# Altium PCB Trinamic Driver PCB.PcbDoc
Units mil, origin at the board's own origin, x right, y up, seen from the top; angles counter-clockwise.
Board outline 920 x 2060 mil, 2 copper layers (Top Layer, Bottom Layer); 22 components, 34 nets, 111 pads, 14 vias.
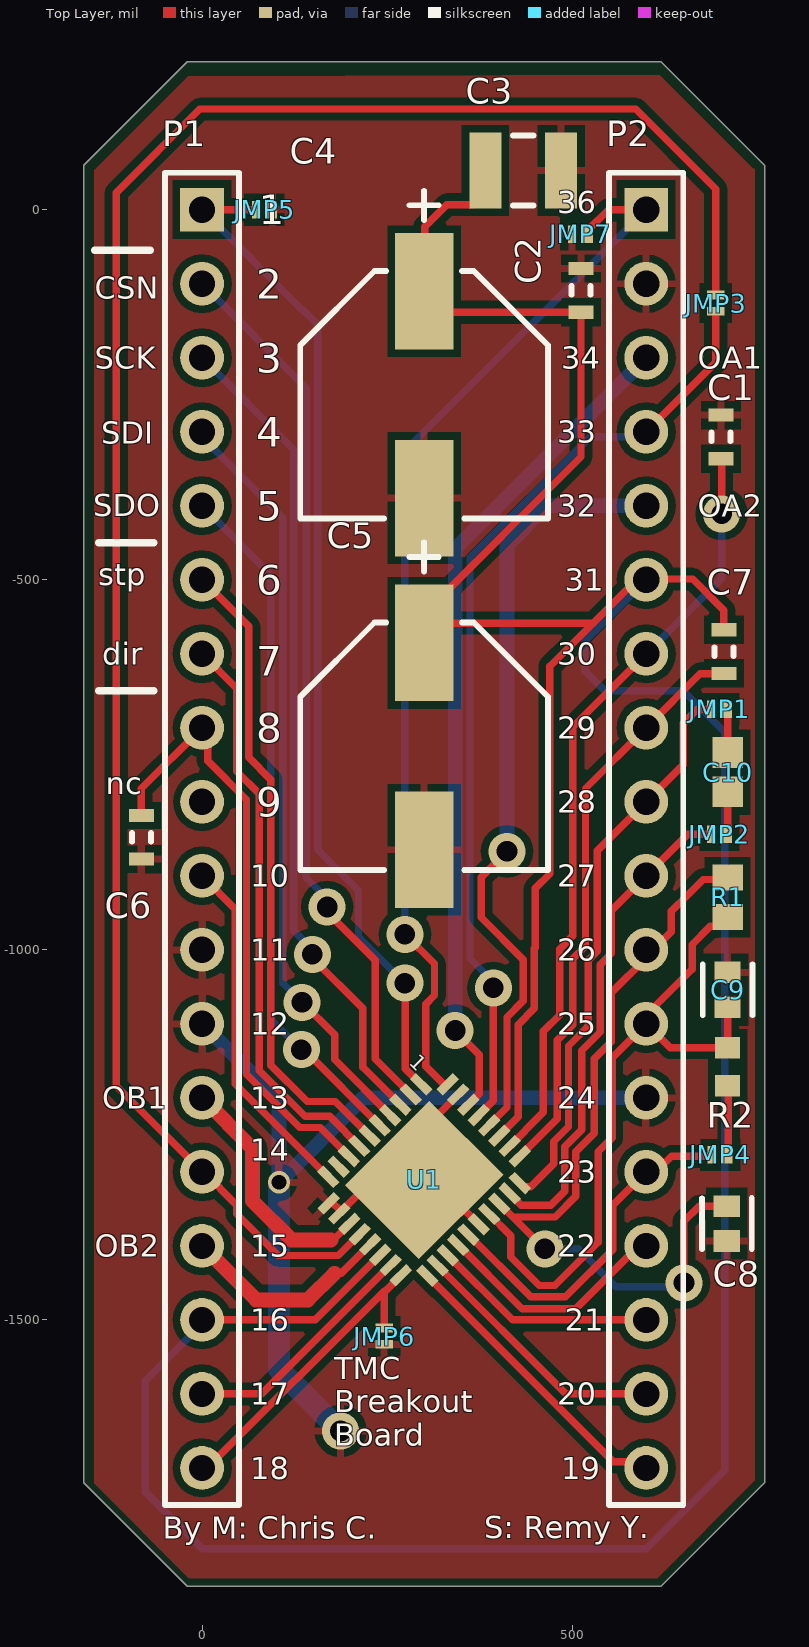
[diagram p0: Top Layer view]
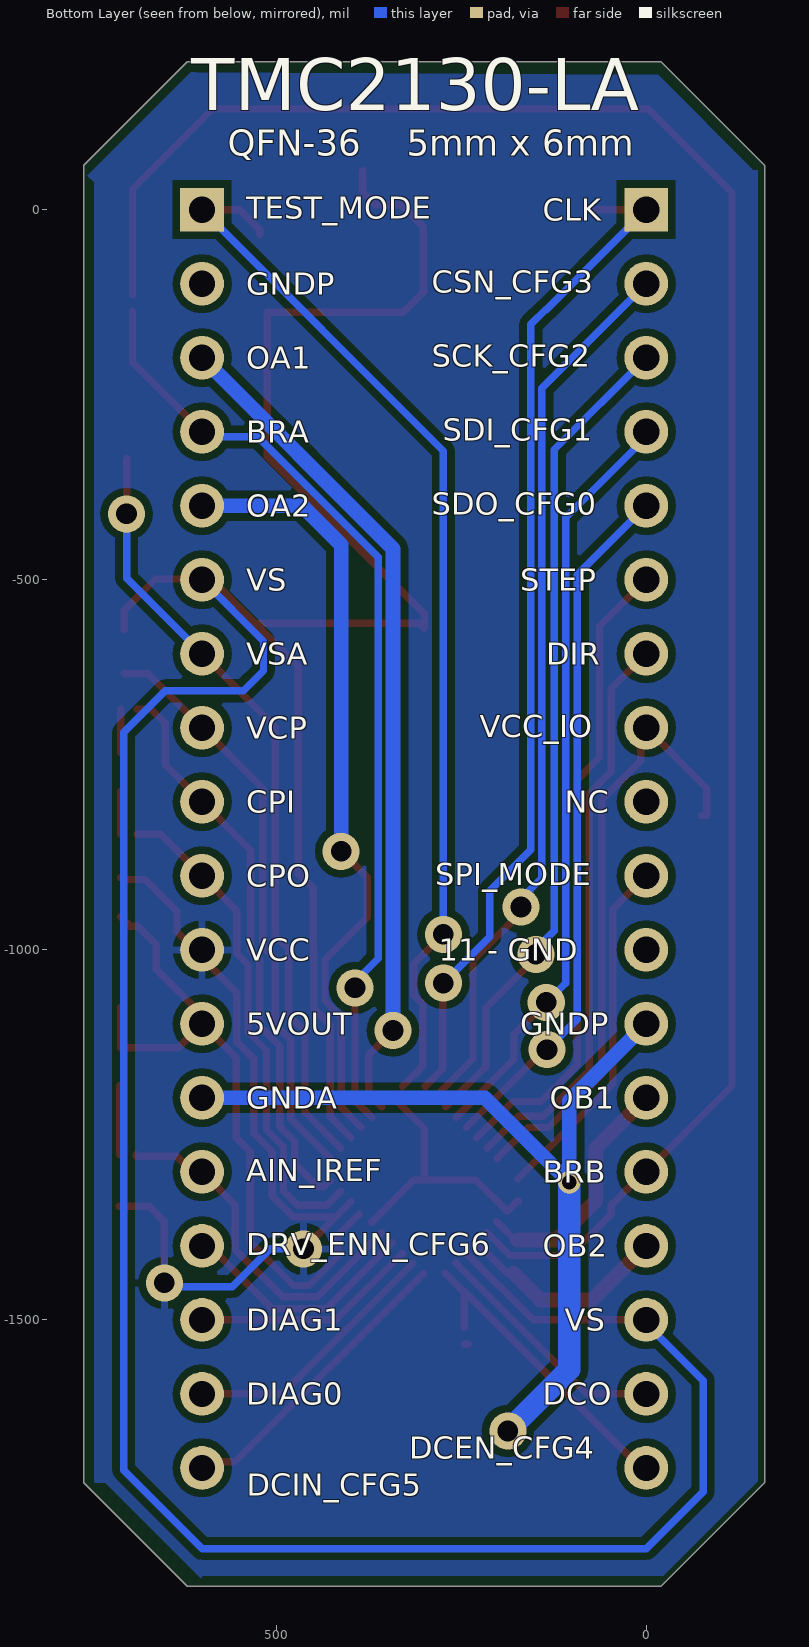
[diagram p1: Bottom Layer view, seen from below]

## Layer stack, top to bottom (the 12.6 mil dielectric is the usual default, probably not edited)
Top Solder: solder mask 0.4, Solder Resist, Dk 3.5
Top Layer: signal copper 1.4
Dielectric 1: dielectric 12.6, FR-4, Dk 4.8
Bottom Layer: signal copper 1.4
Bottom Solder: solder mask 0.4, Solder Resist, Dk 3.5

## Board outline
-160,60 -20,200 620,200 760,60 760,-1720 620,-1860 -20,-1860 -160,-1720

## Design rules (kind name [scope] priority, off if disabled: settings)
Clearance [All] p1: gap=10 ignorepadtopadclearanceinfootprint=FALSE except(0: Arc-Hole Track-Hole SMDPad-Hole THPad-Hole Via-Hole Fill-Hole Poly-Hole Region-Hole Text-Hole; 4.9: SMDPad-SMDPad; 5: Arc-Arc Arc-Track Track-Track; 8: Arc-SMDPad Track-SMDPad)
MinimumSolderMaskSliver [All] p1: minsoldermaskwidth=3
PolygonConnect [All] p1: connectstyle=Relief reliefconductorwidth=10 reliefentries=4 polygonreliefangle="90 Angle" airgapwidth=10
RoutingVias [All] p1: holewidth=28 width=50 viastyle="Through Hole" minholewidth=28 minwidth=50 maxholewidth=28 maxwidth=50
SilkToSilkClearance [All] p1: silktosilkclearance=0
SilkToSolderMaskClearance [IsPad] p1: minsilkscreentomaskgap=0 clearancetoexposedcopper=TRUE
SolderMaskExpansion SolderMaskExpansion_1 [IsVia] p1: expansion=4 istentingtop=TRUE
SolderMaskExpansion [All] p2: expansion=4 istentingtop=FALSE
Width [All] p1: maxlimit=30 minlimit=10 preferedwidth=20 minimp=50.000000 maximp=50.000000 favimp=50.000000
27 further rules are at their usual default settings.

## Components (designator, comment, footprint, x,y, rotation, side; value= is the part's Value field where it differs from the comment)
C1 "CGA3E2X7R1H104K080AA" CAPC1608X90X20LL10 701,-307 r270 top
C2 "CGA3E2X7R1H104K080AA" CAPC1608X90X20LL10 512,-109 r270 top
C3 "C1210C476M4PACTU" CAPC3225X270X50LL20T25 434,53 r180 top
C4 "EEE-FK1H101P" FP-EEE-FK1H101P-MFG 300,-250 r90 top value=100uF
C5 "EEE-FK1H101P" FP-EEE-FK1H101P-MFG 300,-725 r90 top value=100uF
C6 "CGA3E2X7R1H104K080AA" CAPC1608X90X20LL10 -82,-848 r90 top
C7 "CGA3E2X7R1H104K080AA" CAPC1608X90X20LL10 705,-597 r270 top
C8 "C0603C474K4RACTU" FP-C0603C-CF-MFG 709,-1370 r90 top value="0.47 μF"
C9 "C0603C475K9PACTU" FP-C0603-CG-MFG 710,-1054 r90 top value=4.7uF
C10 "CC0603KRX7R9BB223" CAPC1608X90X40ML10T20 710,-760 r270 top
JMP1 "Solder Jump" "Solder Jump" 688,-675 r0 top
JMP2 "Solder Jump" "Solder Jump" 688,-844 r0 top
JMP3 "Solder Jump" "Solder Jump" 694,-115.09 r270 top
JMP4 "Solder Jump" "Solder Jump" 689,-1277 r0 top
JMP5 "Solder Jump" "Solder Jump" 95,0 r180 top
JMP6 "Solder Jump" "Solder Jump" 246,-1511 r270 top
JMP7 "Solder Jump" "Solder Jump" 522,-33 r180 top
P1 "Header 18" HDR1X18 0,0 r270 top
P2 "Header 18" HDR1X18 600,0 r270 top
R1 "CRCW06033R30JNEA" RESC1609X50X30ML10T20 710,-929 r90 top
R2 "ERJ3EKF1002V" RESC1609X55X30LL15T15 710,-1158 r90 top
U1 "TMC2130-LA" QFN-36 300,-1311 r315 top

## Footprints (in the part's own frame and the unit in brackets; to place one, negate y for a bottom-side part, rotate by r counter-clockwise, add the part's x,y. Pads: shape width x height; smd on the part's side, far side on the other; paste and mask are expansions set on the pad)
CAPC1608X90X20LL10 [mm] "Chip Capacitor, 2-Leads, Body 1.70x0.90mm, IPC High Density"
  rect 0.45x0.85 smd: 1(-0.75,0) 2(0.75,0)
  silkscreen extent -0.15,-0.33 0.15,0.33, body extent -0.85,-0.45 0.85,0.45, height 0.9
CAPC1608X90X40ML10T20 [mm] "Chip Capacitor, 2-Leads, Body 1.7x0.9mm, IPC Low Density"
  rect 1.05x1.05 smd: 1(-0.675,0) 2(0.675,0)
  body extent -0.85,-0.45 0.85,0.45, height 0.9
CAPC3225X270X50LL20T25 [mm] "Chip Capacitor, 2-Leads, Body 3.20x2.50mm, IPC High Density"
  rect 1.1x2.6 smd: 1(-1.3,0) 2(1.3,0)
  silkscreen extent -0.35,-1.2 0.35,1.2, body extent -1.7,-1.35 1.7,1.35, height 2.7
FP-C0603-CG-MFG [mm]
  rect 0.75x0.9 smd paste+0 mask+0: 1(-0.6,0) 2(0.6,0)
  silkscreen extent -0.87,-0.85 0.87,0.85, body extent -1.2,-0.6 1.2,0.6, height 0.25
FP-C0603C-CF-MFG [mm]
  rect 0.75x0.9 smd paste+0 mask+0: 1(-0.6,0) 2(0.6,0)
  silkscreen extent -0.87,-0.85 0.88,0.85, body extent -1.2,-0.6 1.2,0.6, height 0.25
FP-EEE-FK1H101P-MFG [mm]
  rect 4x2 smd paste+0 mask+0: 1(-3.55,0) 2(3.55,0)
  silkscreen extent -4.25,-4.25 7,4.25, body extent -5.8,-4.5 5.8,4.5, height 0.25
HDR1X18 [mm] "Connector; Header; 18 Position"
  rect 1.5x1.5 hole 0.9: 1(0,0)
  round 1.5 hole 0.9: 2(2.54,0) 3(5.08,0) 4(7.62,0) 5(10.16,0) 6(12.7,0) 7(15.24,0) 8(17.78,0) 9(20.32,0) 10(22.86,0) 11(25.4,0) 12(27.94,0) 13(30.48,0) 14(33.02,0) 15(35.56,0) 16(38.1,0) 17(40.64,0) 18(43.18,0)
  silkscreen extent -1.27,-1.27 44.45,1.27
QFN-36 [mm]
  rect 0.8x0.3 smd mask+0: 1(-2.4,2.25) 2(-2.4,1.75) 3(-2.4,1.25) 4(-2.4,0.75) 5(-2.4,0.25) 6(-2.4,-0.25) 7(-2.4,-0.75) 8(-2.4,-1.25) 9(-2.4,-1.75) 10(-2.4,-2.25) 19(2.4,-2.25) 20(2.4,-1.75) 21(2.4,-1.25) 22(2.4,-0.75) 23(2.4,-0.25) 24(2.4,0.25) 25(2.4,0.75) 26(2.4,1.25) 27(2.4,1.75) 28(2.4,2.25)
  rect 0.3x0.8 smd mask+0: 11(-1.75,-2.875) 12(-1.25,-2.875) 13(-0.75,-2.875) 14(-0.25,-2.875) 15(0.25,-2.875) 16(0.75,-2.875) 17(1.25,-2.875) 18(1.75,-2.875) 29(1.75,2.9) 30(1.25,2.9) 31(0.75,2.9) 32(0.25,2.9) 33(-0.25,2.9) 34(-0.75,2.9) 35(-1.25,2.9) 36(-1.75,2.9)
  rect 3.6x4.1 smd mask+0: -(0,0)
RESC1609X50X30ML10T20 [mm] "Chip Resistor, 2-Leads, Body 1.55x0.85mm, IPC Low Density"
  rect 0.9x1.05 smd: 1(-0.675,0) 2(0.675,0)
  body extent -0.82,-0.48 0.82,0.48, height 0.5
RESC1609X55X30LL15T15 [mm] "Chip Resistor, 2-Leads, Body 1.75x0.95mm, IPC High Density"
  rect 0.75x0.85 smd: 1(-0.65,0) 2(0.65,0)
  body extent -0.87,-0.48 0.87,0.48, height 0.55
"Solder Jump" [mm]
  rect 0.3x0.6 smd mask+0: 1(0,0) 2(0.559,0)

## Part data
C1 C2 C6 C7: library part CMP-2000-07546-1, "Chip Capacitor, 0.1 uF, +/- 10%, 50 V, -55 to 125 degC, 0603 (1608 Metric), RoHS, Tape and Reel", Capacitance=100nF, Case Code (Imperial)=0603, Case Code (Metric)=1608, Dielectric=X7R, Manufacturer=TDK, Max Operating Temperature=125degC, Min Operating Temperature=-55degC, Package Description="2-Pin Surface Mount Device, Body 1.6 x 0.8 mm", Package Quantity=1, Package Reference=603, Tolerance=10%, Voltage=50V
C3: library part CMP-2000-06020-1, "Chip Capacitor, 47 uF, +/- 20%, 16 V, -55 to 85 degC, 1210 (3225 Metric), RoHS, Tape and Reel", Capacitance=47µF, Manufacturer=Kemet, Operating Temperature=-55°C~85°C, Package / Case=1210(3225Metric), Package Description="2-Pin Surface Mount Device, Body 3.2 x 2.5 mm", Package Reference=1210, Ratings=-, Standard Package=1, Temperature Coefficient=X5R, Tolerance=±20%, Voltage - Rated=16V
C4 C5: library part CMP-05427-000005-1, "CAP ALUM 100UF 20% 50V SMD", Capacitance=100uF, Leakage Current=50uA, Manufacturer="Panasonic Electronic Components", Package=0, Ripple Current=350mA, Temperature="-55°C to +105°C", Temperature Range High=+105°C, Temperature Range Low=-55°C, Tolerance=20%, Voltage Rating=50V
C8: library part CMP-03020-024061-1, "CAP CER 0.47UF 16V X7R 0603", Capacitance="0.47 μF", Manufacturer=KEMET, Package=C0603C-CF, Temperature="-55°C to +125°C", Temperature Characteristic=X7R, Temperature Coefficient=30ppm/°C, Temperature Range High=+125°C, Temperature Range Low=-55°C, Tolerance=0.1, Voltage Rating="16 V"
C9: library part CMP-03020-024641-1, "CAP CER 4.7UF 6.3V X5R 0603", Capacitance=4.7uF, Manufacturer=Kemet, Package=C0603-CG, Temperature="-55°C to +85°C", Temperature Characteristic=X5R, Temperature Coefficient=15%, Temperature Range High=+85°C, Temperature Range Low=-55°C, Tolerance=10%, Voltage Rating=6.3V
C10: library part CMP-2100-03602-1, "Chip Capacitor, 22 nF, +/- 10%, 50 V, -55 to 125 degC, 0603 (1608 Metric), RoHS, Tape and Reel", Capacitance=22nF, Case Code (Imperial)=0603, Case Code (Metric)=1608, Dielectric=X7R, Dielectric Material=Ceramic, Insulation Resistance=100GR, Manufacturer=Yageo, Max Operating Temperature=125degC, Min Operating Temperature=-55degC, Package Description="2-Pin Surface Mount Device, Body 1.6 x 0.8 mm", Package Quantity=1, Tolerance=10%, Voltage Rating=50V
P1 P2: "Header, 18-Pin"
R1: library part CMP-2000-03328-1, Manufacturer="Vishay Dale"
R2: library part CMP-2000-07452-1, "Chip Resistor, 10 KOhm, +/- 1%, 0.1 W, -55 to 155 degC, 0603 (1608 Metric), RoHS, Tape and Reel", Case Code (Imperial)=0603, Case Code (Metric)=1608, Manufacturer=Panasonic, Max Operating Temperature=155degC, Max Power Dissipation=100mW, Min Operating Temperature=-55degC, Package Description="2-Pin Surface Mount Device, Body 1.6 x 0.85 mm", Package Quantity=1, Package Reference=603, Resistance=10KOhm, Temperature Coefficient=100ppm\/degreesC, Tolerance=1%, Voltage Rating=75V
U1: "TMC2130-LA Trinamic Driver QFN-36"

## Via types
v1: diameter 50, hole 28, Top Layer to Bottom Layer, tented both sides, 13 vias
v2: diameter 30, hole 20, Top Layer to Bottom Layer, tented both sides, 1 vias

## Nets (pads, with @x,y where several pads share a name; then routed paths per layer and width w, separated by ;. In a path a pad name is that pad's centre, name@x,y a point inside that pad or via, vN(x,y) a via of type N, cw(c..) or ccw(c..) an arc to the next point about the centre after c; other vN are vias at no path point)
5VOUT: C9.1 P2.12 R1.1 R2.2 U1.25 | length 925.4
  Top Layer w10: U1.25@387.69,-1357.69 U1.25 417,-1386.24 417,-1415 455.48,-1453.48 476.52,-1453.48 535,-1395 535,-1273 554,-1254 554,-1146 P2.12 ; C9.1 R2.2 632.41,-1132.41 P2.12 ; R1.1 697.28,-968.29 686.71,-968.29 662,-993 662,-1026 600,-1088 P2.12
AIN_IREF: JMP4.1 P2.14 U1.23 | length 483.3
  Top Layer w10: U1.23@357.07,-1381.99 444.08,-1469 491,-1469 555,-1405 555,-1345 P2.14 613.27,-1300 634.27,-1279 688.09,-1279 689,-1278.09 JMP4.1
BRA: JMP3.2 P2.4 U1.33 | length 1288.8
  Top Layer w10: U1.33@370.99,-1226.09 393.4,-1203.68 v1(393.4,-1051.4) ; P2.4 694,-206 JMP3.2
  Bottom Layer w10: v1(393.4,-1051.4) 393.4,-1043.11 362,-1011.71 362,-469.68 524.68,-307 P2.4@593,-307
  Bottom Layer w15: P2.4@593,-307 P2.4
BRB: JMP3.1 P1.14 U1.14 | length 2698.4
  Top Layer w10: U1.14@215.79,-1381.29 184.08,-1413 103,-1413 47,-1357 47,-1345 2,-1300 P1.14 -116,-1184 -116,23 -3,136 586,136 694,28 JMP3.1
CLK: JMP5.2 P1.1 U1.1 | length 1381.6
  Top Layer w10: P1.1 JMP5.2 ; v1(274,-1045) 274.73,-1045.73 274.73,-1160.46 U1.1@298.61,-1184.33
  Bottom Layer w10: P1.1 135,-135 136,-135 156,-155 156,-865 211.32,-920.32 211.32,-982.32 v1(274,-1045)
CPI: JMP1.1 P2.9 U1.28 | length 777.7
  Top Layer w10: U1.28@426.67,-1312.39 427.95,-1312.39 435.64,-1320.08 443.92,-1320.08 475,-1289 475,-1259 495,-1239 495,-1130 522,-1103 522,-1014 534,-1002 534,-866 P2.9 650,-750 650,-694 669,-675 JMP1.1
CPO: JMP2.1 P2.10 U1.27 | length 675.6
  Top Layer w10: U1.27@412.75,-1326.31 431.44,-1345 471,-1345 490,-1326 490,-1266 513,-1243 513,-1136 538,-1111 538,-1020 553,-1005 553,-947 P2.10 656,-844 JMP2.1
CSN_CFG3: P1.2 U1.2 | length 1216.2
  Top Layer w10: v1(169,-942) 169,-949 234,-1014 234,-1147.56 U1.2@284.69,-1198.25
  Bottom Layer w10: P1.2 141,-241 141,-903 169,-931 v1(169,-942)
DCEN_CFG4: JMP6.1 P1.18 U1.18 | length 430.8
  Top Layer w10: P1.18 7.16,-1700 246,-1461.16 JMP6.1 ; 246,-1462.44 U1.18@271.47,-1436.97
DCIN_CFG5: P2.18 U1.19 | length 407.3
  Top Layer w10: U1.19@301.39,-1437.67 555.47,-1691.75 591.75,-1691.75 P2.18
DCO: P1.17 U1.17 | length 330.8
  Top Layer w10: P1.17 80.6,-1600 U1.17@257.55,-1423.05
DIAG0: P2.17 U1.20 | length 357.7
  Top Layer w10: U1.20@315.31,-1423.75 491.56,-1600 P2.17
DIAG1: P2.16 U1.21 | length 308.1
  Top Layer w10: U1.21@329.23,-1409.83 419.4,-1500 P2.16
DIR: P1.7 U1.7 | length 776.4
  Top Layer w10: P1.7 47,-647 47,-759 77,-789 77,-1163 139,-1225 172.24,-1225 U1.7@215.09,-1267.85
DRV_ENN_CFG6: P2.15 U1.22 | length 329
  Top Layer w10: U1.22@343.15,-1395.91 432.24,-1485 505,-1485 590,-1400 P2.15
GND: C1.1 C2.1 C3.1 C4.1 C5.1 C6.1 C8.1 C9.2 JMP5.1 JMP6.2 JMP7.2 P1.11 P1.12 P2.2 P2.13 U1.11 U1.12 U1.24 U1.35 U1.- | length 1564.5
  Top Layer w10: U1.11@172.75,-1339.53 174.03,-1339.53 187.95,-1353.45 230.4,-1311 U1.- ; JMP6.2@240.09,-1533 JMP6.2 ; U1.35@343.15,-1198.25 300,-1241.4 U1.- ; U1.24@370.99,-1368.07 313.92,-1311 U1.- ; P2.13@591.47,-1208.53 P2.13
  Bottom Layer w20: P1.12 104,-1204 v2(104,-1314) 218,-1200 P2.13
  Bottom Layer w30: v2(104,-1314) 104,-1567 v1(187,-1650)
MISO_CFG0: P1.5 U1.5 | length 948.9
  Top Layer w10: P1.5 P1.5@6,-400 ; v1(134,-1135) 137.92,-1135 U1.5@242.93,-1240.01
  Bottom Layer w10: P1.5 93,-493 93,-1094 v1(134,-1135)
MOSI_CFG1: P1.4 U1.4 | length 1031
  Top Layer w10: P1.4@0,-302 P1.4 ; v1(135,-1071) 179,-1115 179,-1148.24 U1.4@256.85,-1226.09
  Bottom Layer w10: P1.4@-2.5,-304.5 108.9,-415.9 108.9,-1044.9 v1(135,-1071)
NetC10_1: C10.1 JMP1.2 | length 58.4
  Top Layer w10: C10.1 JMP1.2
NetC10_2: C10.2 JMP2.2 | length 57.4
  Top Layer w10: JMP2.2 C10.2
NetJMP4_2: JMP4.2 R2.1 | length 93.4
  Top Layer w10: JMP4.2 R2.1@711,-1183.59
OA1: P2.3 U1.34 | length 1145.5
  Top Layer w10: v1(342,-1109) 374.6,-1141.6 374.6,-1194.64 U1.34@357.07,-1212.17
  Top Layer w20: v1(342,-1109) v1@346,-1113
  Bottom Layer w20: v1(342,-1109) 342,-458 P2.3
OA2: P2.5 U1.32 | length 1055.4
  Top Layer w10: U1.32@384.91,-1240.01 412,-1212.92 412,-1091 434,-1069 434,-1013.28 377,-956.28 377,-902 v1(412,-867)
  Bottom Layer w20: v1(412,-867) 412,-453 465,-400 P2.5
OB1: P1.13 U1.13 | length 333.2
  Top Layer w10: 174,-1392 177.24,-1392 U1.13@201.87,-1367.37
  Top Layer w20: P1.13 68,-1268 68,-1339 121,-1392 174,-1392
OB2: P1.15 U1.15 | length 292.2
  Top Layer w10: 179,-1437 187.92,-1437 U1.15@229.71,-1395.21
  Top Layer w20: P1.15 73,-1473 143,-1473 179,-1437
SCK_CFG2: P1.3 U1.3 | length 1133.3
  Top Layer w10: P1.3@0,-209 P1.3 ; v1(149,-1006) 149,-1011 217,-1079 217,-1158.4 U1.3@270.77,-1212.17
  Bottom Layer w10: P1.3 124,-324 124,-974.43 149,-999.43 v1(149,-1006)
SPI_MODE: P1.10 U1.10 | length 481.4
  Top Layer w10: P1.10 45,-945 45,-1181.27 U1.10@173.33,-1309.61
STEP: P1.6 U1.6 | length 871.1
  Top Layer w10: P1.6 63,-563 63,-740 93,-770 93,-1156 142,-1205 180.08,-1205 U1.6@229.01,-1253.93
TST_MODE: JMP7.1 P2.1 U1.36 | length 1447.3
  Top Layer w10: v1(274,-979) 314,-1019 314,-1061.57 302,-1073.57 302,-1157.1 U1.36@329.23,-1184.33 ; JMP7.1 522,-27.09 549.09,0 P2.1
  Bottom Layer w10: v1(274,-979) 274,-326 P2.1
VCC: C8.2 P2.11 R1.2 U1.26 | length 1079.1
  Top Layer w10: U1.26@398.83,-1340.23 419.6,-1361 ; v1(463,-1404) 462.6,-1404 419.6,-1361 ; P2.11@600,-1011 553,-1058 553,-1124 530,-1147 530,-1248 505,-1273 505,-1333 477,-1361 419.6,-1361 ; P2.11 609.47,-1000 633.87,-975.61 633.87,-948.13 655.18,-926.82 677.04,-904.96 707.47,-904.96 R1.2 ; v1(651,-1450) 651,-1367 671.62,-1346.38 C8.2 C8.2@711.95,-1346.38
  Bottom Layer w10: v1(463,-1404) 508,-1404 559,-1455 646,-1455 v1(651,-1450)
VCC_IO: C6.2 P1.8 U1.8 | length 841.5
  Top Layer w10: C6.2@-74.13,-818.47 C6.2 -82,-782 P1.8 7.53,-707.53 7.53,-744.53 60,-797 60,-1168 132,-1240 159.4,-1240 U1.8@201.17,-1281.77
VCP: C7.2 P2.8 U1.29 | length 789
  Top Layer w10: U1.29@426.67,-1281.77 480,-1228.44 480,-1122 501,-1101 501,-1012 518,-995 518,-782 P2.8 673.27,-626.73 704.8,-626.73 C7.2
VS: C2.2 C3.2 C4.2 C5.2 C7.1 P1.16 P2.6 U1.16 U1.31 | length 4964.1
  Top Layer w10: P1.16 152.76,-1500 U1.16@243.63,-1409.13 ; C3.2 382.82,23.47 366.17,6.82 330.82,6.82 301,-23 301,-109.24 C4.2 328.29,-138.53 C2.2 512,-333.87 300,-545.87 300,-565.55 307.05,-558.5 528.5,-558.5 ; U1.31@398.83,-1253.93 427,-1225.76 427,-1101 449,-1079 449,-998 450,-997 450,-917 470,-897 470,-617 528.5,-558.5 ; C7.1 705,-541 663,-499 601,-499 P2.6 587,-500 528.5,-558.5
  Bottom Layer w10: P1.16 0,-1505 -77,-1582 -77,-1732 0,-1809 600,-1809 706,-1703 706,-706 650,-650 544,-650 517,-623 517,-583 P2.6
VSA: C1.2 P2.7 U1.30 | length 1051.5
  Top Layer w10: U1.30@412.75,-1267.85 461,-1219.6 461,-1110 483,-1088 483,-999 501,-981 501,-699 P2.7 ; C1.2 702,-337.53 v1(702,-411)
  Bottom Layer w10: P2.7 702,-498 v1(702,-411)
pads on no net: P1.9 U1.9

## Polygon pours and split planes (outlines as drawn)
VCC on Bottom Layer "VCC_L02_P001" (solid, remove dead copper, pour order 1): -16,182 -145,53 -151,53 -151,-1718 -23,-1846 599,-1846 602,-1849 731,-1720 746,-1720 746,37 755,46 615,186 608,186
GND on Top Layer "GND_L01_P000" (solid, remove dead copper, pour order 0): -19,180 -146,53 -146,-1721 -18,-1849 615,-1849 747,-1717 747,55 745,55 618,182

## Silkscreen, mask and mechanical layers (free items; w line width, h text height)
Top Overlay:
  lines w10: -145,-55 -70,-55 ; -140,-650 -65,-650 ; -140,-450 -65,-450
  text "36" at 480.02,-5 h30
  text "1" at 76.67,-19.99 h40
  text "CSN" at -144.97,-120 h30
  text "2" at 73.34,-119.99 h40
  text "SCK" at -144.97,-215 h30
  text "34" at 485.02,-215 h30
  text "OA1" at 670.02,-215 h30
  text "3" at 73.34,-219.99 h40
  text "33" at 480.02,-315 h30
  text "SDI" at -135.98,-316 h30
  text "4" at 73.34,-319.99 h40
  text "SDO" at -146.97,-414 h30
  text "32" at 480.02,-415 h30
  text "OA2" at 670.03,-415 h30
  text "5" at 73.34,-419.99 h40
  text "stp" at -139.98,-507.5 h30
  text "31" at 490.01,-515 h30
  text "6" at 73.34,-519.99 h40
  text "dir" at -134.98,-615 h30
  text "30" at 480.02,-615 h30
  text "7" at 73.34,-629.99 h40
  text "29" at 480.02,-715 h30
  text "8" at 73.34,-719.99 h40
  text "nc" at -129.98,-790 h30
  text "28" at 480.02,-815 h30
  text "9" at 73.34,-819.99 h40
  text "10" at 65.01,-915 h30
  text "27" at 480.02,-915 h30
  text "11" at 65.01,-1015 h30
  text "26" at 480.02,-1015 h30
  text "12" at 65.01,-1115 h30
  text "25" at 480.02,-1115 h30
  text "OB1" at -134.98,-1215 h30
  text "13" at 65.01,-1215 h30
  text "24" at 480.02,-1215 h30
  text "14" at 65.01,-1285 h30
  text "23" at 480.02,-1315 h30
  text "OB2" at -144.97,-1415 h30
  text "15" at 65.01,-1415 h30
  text "22" at 480.02,-1415 h30
  text "16" at 65.01,-1515 h30
  text "21" at 490.01,-1515 h30
  text "17" at 65.01,-1615 h30
  text "20" at 480.02,-1615 h30
  text "TMC / Breakout / Board" at 178.5,-1670 h30
  text "18" at 65.01,-1715 h30
  text "19" at 485.01,-1715 h30
  text "S: Remy Y." at 381,-1795 h30
  text "By M: Chris C." at -53,-1796 h30
Bottom Overlay:
  text "TMC2130-LA" at 614.68,111.47 h120
  text "QFN-36    5mm x 6mm" at 565.58,61.46 h60
  text "TEST_MODE" at 540,-12.5 h30
  text "CLK" at 139.97,-15 h30
  text "CSN_CFG3" at 289.93,-112.5 h30
  text "GNDP" at 540,-115 h30
  text "SCK_CFG2" at 289.93,-212.5 h30
  text "OA1" at 540,-215 h30
  text "SDI_CFG1" at 274.93,-312.5 h30
  text "BRA" at 540,-315 h30
  text "SDO_CFG0" at 289.93,-412.5 h30
  text "OA2" at 540,-415 h30
  text "STEP" at 169.96,-515 h30
  text "VS" at 540,-515 h30
  text "DIR" at 134.98,-615 h30
  text "VSA" at 540,-615 h30
  text "VCC_IO" at 224.95,-712.5 h30
  text "VCP" at 540,-715 h30
  text "NC" at 109.98,-815 h30
  text "CPI" at 540,-815 h30
  text "SPI_MODE" at 284.93,-912.5 h30
  text "CPO" at 540,-915 h30
  text "11 - GND" at 279.93,-1015 h30
  text "VCC" at 540,-1015 h30
  text "GNDP" at 169.96,-1115 h30
  text "5VOUT" at 540,-1115 h30
  text "OB1" at 129.98,-1215 h30
  text "GNDA" at 540,-1215 h30
  text "AIN_IREF" at 540,-1312.5 h30
  text "BRB" at 139.97,-1315 h30
  text "DRV_ENN_CFG6" at 540,-1412.5 h30
  text "OB2" at 139.97,-1415 h30
  text "VS" at 109.98,-1515 h30
  text "DIAG1" at 540,-1515 h30
  text "DCO" at 139.97,-1615 h30
  text "DIAG0" at 540,-1615 h30
  text "DCEN_CFG4" at 319.92,-1687.5 h30
  text "DCIN_CFG5" at 539.92,-1737.5 h30
Mechanical 1:
  the board outline again, w10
